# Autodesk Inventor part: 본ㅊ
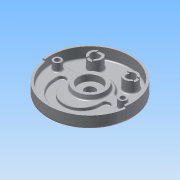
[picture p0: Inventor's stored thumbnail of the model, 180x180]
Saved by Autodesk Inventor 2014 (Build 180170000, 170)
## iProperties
Created: 2015-06
Part Number: 본ㅊ
Material: 알루미늄 6061
Document SubType Name: Modeling
Designer: Administrator
Density: 2.71 g/cm^3
Appearance: 알루미늄 - 평지
Mass: 1070.94 g
Surface Area: 1034.54 cm^2
Volume: 395.182 cm^3
Author: Administrator
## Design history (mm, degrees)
sketch "스케치1"
  geometry: C1 r 95 at (0, 0); 1 further point
  constraints: 1 centre point, 1 coincident
  dimensions: "d0" = 190 diameter of C1
extrude "돌출1" new body sketch "스케치1" distance "d1" = 32; taper "d2" = 0 deg
sketch "스케치2"
  geometry: C1 r 95 at (0, 0) reference; C2 r 90 at (0, 0)
  constraints: 1 centre point, 1 coincident
  dimensions: "d7" = 180 diameter of C2
extrude "돌출2" cut sketch "스케치2" distance "d8" = 18; taper "d9" = 0 deg
sketch "스케치4"
  geometry: L1 (-88.566, 16)-(-38.833, 16); L2 (38.833, 16)-(88.566, 16); A1 r 90 centre (0, 0) between (88.566, 16) and (-88.566, 16) reference; A2 r 42 centre (0, 0) between (-38.833, 16) and (38.833, 16); 1 further point
  constraints: 4 end point, 4 point on circle, 2 horizontal, 1 centre point, 1 coincident, 1 vertical alignment
  dimensions: "d12" = 84 diameter of A2; "d14" = 16 distance of A1.centre point (0, 16); "d15" = 38.83298 distance of point (0, 16) L1.end; "d16" = 38.83298 distance of L2.start point (0, 16)
extrude "돌출4" cut sketch "스케치4" distance "d19" = 7; taper "d20" = 0 deg
sketch "스케치5"
  geometry: L1 (0, 0)-(95, 0); L2 (0, 0)-(-95, 0); L3 (0, 0)-(-94.075, -13.221); L4 (0, 0)-(94.075, -13.221); A1 r 95 centre (0, 0) between (95, 0) and (-95, 0) reference
  constraints: 8 end point, 4 point on circle, 1 collinear, 1 horizontal
  dimensions: "d21" = 8 deg angle of L3 L2; "d22" = 8 deg angle of L4 L1
extrude "돌출5" cut sketch "스케치5" distance "d23" = 5; taper "d24" = 0 deg
sketch "스케치6"
  geometry: C1 r 15 at (-40, 52); C2 r 15 at (40, 52); A1 r 90 centre (0, 0) between (88.566, 16) and (-88.566, 16) reference
  constraints: 2 centre point, 1 equal radius, 1 horizontal alignment
  dimensions: "d25" = 52 vertical distance of A1.centre C2.centre; "d26" = 30 diameter of C1; "d27" = 40 horizontal distance of A1.centre C1.centre; "d28" = 40 horizontal distance of C2.centre A1.centre
extrude "돌출6" join sketch "스케치6" distance "d29" = 25; taper "d30" = 0 deg
hole "구멍1" diameter "d33" = 20; stored, may be unused: countersink angle "d37" = 90 deg, drill point angle "d39" = 118 deg; dims "d31" = 10, "d32" = 10, "d34" = 6, "d35" = 4, "d36" = 2, "d38" = 8
hole "구멍2" diameter "d42" = 20; stored, may be unused: countersink angle "d46" = 90 deg, drill point angle "d48" = 118 deg; dims "d40" = 10, "d41" = 10, "d43" = 6, "d44" = 4, "d45" = 2, "d47" = 8
sketch "스케치7"
  geometry: L1 (-6, 20.367)-(6, 20.367); L2 (6, 20.367)-(6, -20.367); L3 (6, -20.367)-(-6, -20.367); L4 (-6, -20.367)-(-6, 20.367); L5 (-6, 20.367)-(6, -20.367); L6 (6, 20.367)-(-6, -20.367); L7 (58.462, 6)-(101.538, 6); L8 (101.538, 6)-(101.538, -6); L9 (101.538, -6)-(58.462, -6); L10 (58.462, -6)-(58.462, 6); L11 (58.462, 6)-(101.538, -6); L12 (101.538, 6)-(58.462, -6); C1 r 15 at (0, 0) reference; C2 r 15 at (80, 0) reference; 1 further point
  constraints: 24 end point, 4 midpoint, 4 parallel, 2 horizontal, 2 perpendicular
  dimensions: "d49" = 12 distance of L1.start L1.end; "d50" = 12 distance of L7.end L8.end; "d51" = 43.07513 distance between parallel lines of L8 L10; "d52" = 40.7331 distance between parallel lines of L3 L1
extrude "돌출7" cut sketch "스케치7" distance "d53" = 3; taper "d54" = 0 deg
sketch "스케치8"
  geometry: C1 r 35 at (0, 0); A1 r 90 centre (0, 0) between (-88.566, 16) and (88.566, 16) reference
  constraints: 1 centre point, 1 coincident
  dimensions: "d55" = 70 diameter of C1
extrude "돌출8" join sketch "스케치8" distance "d56" = 10; taper "d57" = -10 deg
sketch "스케치9"
  geometry: C1 r 95 at (0, 0) reference; C2 r 26 at (0, 0)
  constraints: 1 centre point, 1 coincident
  dimensions: "d58" = 52 diameter of C2
extrude "돌출9" join sketch "스케치9" distance "d59" = 12; taper "d60" = -15 deg
hole "구멍3" diameter "d63" = 23; stored, may be unused: countersink angle "d67" = 90 deg, drill point angle "d69" = 118 deg; dims "d61" = 10, "d62" = 10, "d64" = 6, "d65" = 50, "d66" = 15, "d68" = 8
sketch "스케치10"
  geometry: L1 (-59, -19)-(-59, -14); L2 (-41, -19)-(-41, -14); L3 (41, -19)-(41, -14); L4 (59, -19)-(59, -14); L5 (41, -14)-(59, -14); L6 (-41, -14)-(-59, -14); C1 r 35 at (0, 0) reference; A1 r 41 centre (0, -19) between (-41, -19) and (41, -19); A2 r 59 centre (0, -19) between (-59, -19) and (59, -19); 5 further points
  constraints: 12 end point, 4 perpendicular, 4 point on circle, 4 tangent, 2 centre point, 2 coincident, 2 horizontal alignment, 2 midpoint, 2 vertical alignment, 1 parallel, 4 other
  dimensions: "d73" = 59 radius of A2; "d74" = 41 radius of A1; "d76" = 19 distance of C1.centre A2.centre; "d77" = 14 distance of C1.centre point (0, -14); "d78" = 14 distance from line of C1.centre L6; "d79" = 0 distance between parallel lines of L6 L5; "d80" = 29.56636 distance from line of point (88.566, 16) L4
extrude "돌출10" cut sketch "스케치10" distance "d81" = 7; taper "d82" = 0 deg
sketch "스케치11"
  geometry: C1 r 35 at (0, 0) reference; C2 r 9 at (-74, 0); C3 r 9 at (74, 0); A1 r 42 centre (0, 0) between (38.833, 16) and (-38.833, 16) reference; A2 r 15 centre (-40, 52) between (-46, 65.748) and (-46, 38.252) reference; A3 r 15 centre (40, 52) between (53.748, 58) and (26.252, 58) reference
  constraints: 2 centre point, 1 equal radius
  dimensions: "d83" = 18 diameter of C2; "d84" = 52 vertical distance of C2.centre A2.centre; "d85" = 52 vertical distance of C3.centre A3.centre; "d86" = 74 distance of A1.centre C2.centre; "d87" = 74 distance of C3.centre C1.centre
extrude "돌출11" join sketch "스케치11" distance "d88" = 18; taper "d89" = 0 deg
sketch "스케치12"
  geometry: C1 r 9 at (-74, 0) reference; C2 r 9 at (74, 0) reference; 2 further points
  constraints: 2 coincident
hole "구멍4" sketch "스케치12" at (-74, 0), (74, 0) diameter "d90" = 11; stored, may be unused: countersink angle "d94" = 90 deg, drill point angle "d96" = 118 deg; dims "d91" = 6, "d92" = 18, "d93" = 11, "d95" = 8
sketch "스케치13"
  geometry: C1 r 95 at (0, 0) reference; C2 r 68 at (0, 0)
  constraints: 1 centre point, 1 coincident, 1 other
  dimensions: "d97" = 136 diameter of C2
feature "엠보싱1" sketch "스케치13" dims "d98" = 0.5, "d99" = 0
fillet "모깎기1" dims "d100" = 10
fillet "모깎기2" dims "d101" = 0.3
fillet "모깎기3" dims "d102" = 5
fillet "모깎기4" dims "d103" = 1
chamfer "모따기1" distance "d104" = 1; stored, may be unused: second distance "d105" = 2, angle "d106" = 45 deg
fillet "모깎기5" dims "d107" = 3
chamfer "모따기2" distance "d110" = 1; stored, may be unused: second distance "d111" = 2, angle "d112" = 45 deg
fillet "모깎기8" dims "d113" = 3
fillet "모깎기9" dims "d114" = 3
fillet "모깎기10" dims "d115" = 3
fillet "모깎기11" dims "d116" = 3
fillet "모깎기12" dims "d117" = 3
node "솔리드1"
other parameters: "d71" = 59, "d72" = 41
